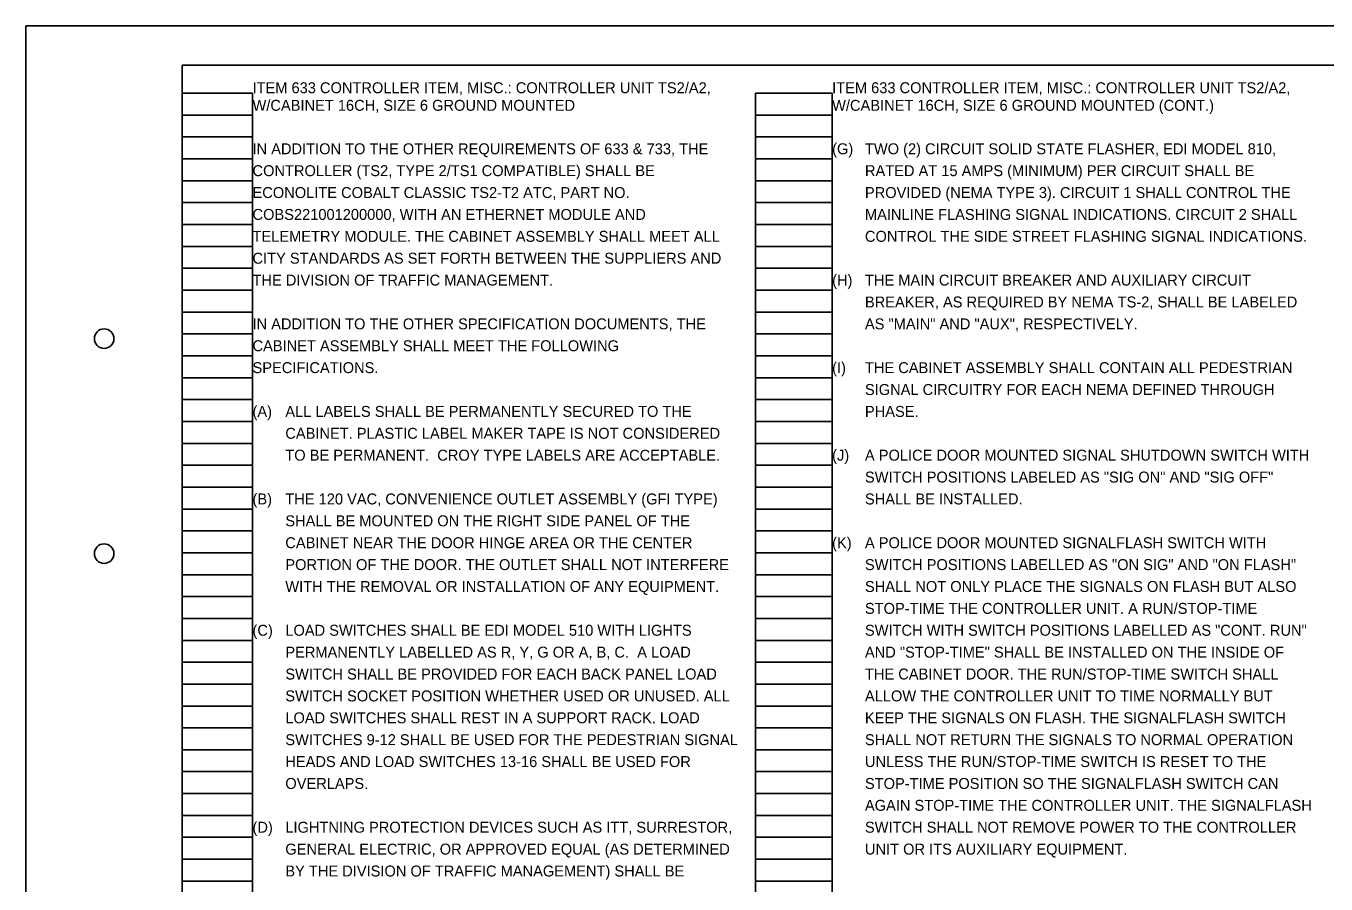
# Model space of a CAD drawing. Extents: x -38 to 65, y -51 to 25.
# Drawn here: x -0.51 to 16.14, y 3.51 to 14.49 of the extents above; entities that cross this region are included whole.
import ezdxf

# ---------------------------------------------------------------- set-up
doc = ezdxf.new("R2010")
doc.units = 0
for name, color, linetype in [('PF_P_Text', 7, 'Continuous'), ('SC_Scratch1', 7, 'Continuous'), ('SH_Cut_Line', 7, 'Continuous'), ('SH_Data', 7, 'Continuous')]:
    doc.layers.add(name, color=color, linetype=linetype)

msp = doc.modelspace()

# ---------------------------------------------------------------- linework, layer by layer
at = {"layer": 'PF_P_Text'}
msp.add_lwpolyline([(1.494, 13.992), (32.994, 13.992), (32.994, -7.008), (1.494, -7.008)], close=True, dxfattribs=at)
for centre in [(0.494, 10.492), (0.494, 7.742)]:
    msp.add_circle(centre, 0.125, dxfattribs=at)
at = {"layer": 'SC_Scratch1'}
for p, q in [((1.494, -6.528), (1.494, 13.632)), ((1.494, 13.632), (2.394, 13.632)), ((2.394, -6.528), (2.394, 13.632)), ((8.834, -6.528), (8.834, 13.632)), ((8.834, 13.632), (9.814, 13.632)), ((9.814, -6.528), (9.814, 13.632)), ((1.494, 13.352), (2.394, 13.352)), ((8.834, 13.352), (9.814, 13.352)), ((1.494, 13.072), (2.394, 13.072)), ((8.834, 13.072), (9.814, 13.072)), ((1.494, 12.792), (2.394, 12.792)), ((8.834, 12.792), (9.814, 12.792)), ((1.494, 12.512), (2.394, 12.512)), ((8.834, 12.512), (9.814, 12.512)), ((1.494, 12.232), (2.394, 12.232)), ((8.834, 12.232), (9.814, 12.232)), ((1.494, 11.952), (2.394, 11.952)), ((8.834, 11.952), (9.814, 11.952)), ((1.494, 11.672), (2.394, 11.672)), ((8.834, 11.672), (9.814, 11.672)), ((1.494, 11.392), (2.394, 11.392)), ((8.834, 11.392), (9.814, 11.392)), ((1.494, 11.112), (2.394, 11.112)), ((8.834, 11.112), (9.814, 11.112)), ((1.494, 10.832), (2.394, 10.832)), ((8.834, 10.832), (9.814, 10.832)), ((1.494, 10.552), (2.394, 10.552)), ((8.834, 10.552), (9.814, 10.552)), ((1.494, 10.272), (2.394, 10.272)), ((8.834, 10.272), (9.814, 10.272)), ((1.494, 9.992), (2.394, 9.992)), ((8.834, 9.992), (9.814, 9.992)), ((1.494, 9.712), (2.394, 9.712)), ((8.834, 9.712), (9.814, 9.712)), ((1.494, 9.432), (2.394, 9.432)), ((8.834, 9.432), (9.814, 9.432)), ((1.494, 9.152), (2.394, 9.152)), ((8.834, 9.152), (9.814, 9.152)), ((1.494, 8.872), (2.394, 8.872)), ((8.834, 8.872), (9.814, 8.872)), ((1.494, 8.592), (2.394, 8.592)), ((8.834, 8.592), (9.814, 8.592)), ((1.494, 8.312), (2.394, 8.312)), ((8.834, 8.312), (9.814, 8.312)), ((1.494, 8.032), (2.394, 8.032)), ((8.834, 8.032), (9.814, 8.032)), ((1.494, 7.752), (2.394, 7.752)), ((8.834, 7.752), (9.814, 7.752)), ((1.494, 7.472), (2.394, 7.472)), ((8.834, 7.472), (9.814, 7.472)), ((1.494, 7.192), (2.394, 7.192)), ((8.834, 7.192), (9.814, 7.192)), ((1.494, 6.912), (2.394, 6.912)), ((8.834, 6.912), (9.814, 6.912)), ((1.494, 6.632), (2.394, 6.632)), ((8.834, 6.632), (9.814, 6.632)), ((1.494, 6.352), (2.394, 6.352)), ((8.834, 6.352), (9.814, 6.352)), ((1.494, 6.072), (2.394, 6.072)), ((8.834, 6.072), (9.814, 6.072)), ((1.494, 5.792), (2.394, 5.792)), ((8.834, 5.792), (9.814, 5.792)), ((1.494, 5.512), (2.394, 5.512)), ((8.834, 5.512), (9.814, 5.512)), ((1.494, 5.232), (2.394, 5.232)), ((8.834, 5.232), (9.814, 5.232)), ((1.494, 4.952), (2.394, 4.952)), ((8.834, 4.952), (9.814, 4.952)), ((1.494, 4.672), (2.394, 4.672)), ((8.834, 4.672), (9.814, 4.672)), ((1.494, 4.392), (2.394, 4.392)), ((8.834, 4.392), (9.814, 4.392)), ((1.494, 4.112), (2.394, 4.112)), ((8.834, 4.112), (9.814, 4.112)), ((1.494, 3.832), (2.394, 3.832)), ((8.834, 3.832), (9.814, 3.832)), ((1.494, 3.552), (2.394, 3.552)), ((8.834, 3.552), (9.814, 3.552))]:
    msp.add_line(p, q, dxfattribs=at)
at = {"layer": 'SH_Cut_Line'}
msp.add_lwpolyline([(-0.506, -7.508), (33.494, -7.508), (33.494, 14.492), (-0.506, 14.492)], close=True, dxfattribs=at)

# ---------------------------------------------------------------- texts
at = {"layer": 'SH_Data'}
for s, p in [('ITEM 633 CONTROLLER ITEM, MISC.: CONTROLLER UNIT TS2/A2, ', (2.394, 13.632)), ('ITEM 633 CONTROLLER ITEM, MISC.: CONTROLLER UNIT TS2/A2, ', (9.814, 13.632)), ('W/CABINET 16CH, SIZE 6 GROUND MOUNTED', (2.394, 13.407)), ('W/CABINET 16CH, SIZE 6 GROUND MOUNTED (CONT.)', (9.814, 13.407)), ('IN ADDITION TO THE OTHER REQUIREMENTS OF 633 & 733, THE ', (2.394, 12.851)), ('(G)', (9.814, 12.851)), ('TWO (2) CIRCUIT SOLID STATE FLASHER, EDI MODEL 810, ', (10.234, 12.851)), ('CONTROLLER (TS2, TYPE 2/TS1 COMPATIBLE) SHALL BE ', (2.394, 12.571)), ('RATED AT 15 AMPS (MINIMUM) PER CIRCUIT SHALL BE ', (10.234, 12.571)), ('ECONOLITE COBALT CLASSIC TS2-T2 ATC, PART NO. ', (2.394, 12.291)), ('PROVIDED (NEMA TYPE 3). CIRCUIT 1 SHALL CONTROL THE ', (10.234, 12.291)), ('COBS221001200000, WITH AN ETHERNET MODULE AND ', (2.394, 12.011)), ('MAINLINE FLASHING SIGNAL INDICATIONS. CIRCUIT 2 SHALL ', (10.234, 12.011)), ('TELEMETRY MODULE. THE CABINET ASSEMBLY SHALL MEET ALL ', (2.394, 11.731)), ('CONTROL THE SIDE STREET FLASHING SIGNAL INDICATIONS.', (10.234, 11.731)), ('CITY STANDARDS AS SET FORTH BETWEEN THE SUPPLIERS AND ', (2.394, 11.451)), ('(H)', (9.814, 11.171)), ('THE DIVISION OF TRAFFIC MANAGEMENT.', (2.394, 11.171)), ('THE MAIN CIRCUIT BREAKER AND AUXILIARY CIRCUIT ', (10.234, 11.171)), ('BREAKER, AS REQUIRED BY NEMA TS-2, SHALL BE LABELED ', (10.234, 10.891)), ('IN ADDITION TO THE OTHER SPECIFICATION DOCUMENTS, THE ', (2.394, 10.611)), ('AS "MAIN" AND "AUX", RESPECTIVELY. ', (10.234, 10.611)), ('CABINET ASSEMBLY SHALL MEET THE FOLLOWING ', (2.394, 10.331)), ('SPECIFICATIONS.', (2.394, 10.051)), ('(I)', (9.814, 10.051)), ('THE CABINET ASSEMBLY SHALL CONTAIN ALL PEDESTRIAN ', (10.234, 10.051)), ('SIGNAL CIRCUITRY FOR EACH NEMA DEFINED THROUGH ', (10.234, 9.771)), ('(A)', (2.394, 9.491)), ('ALL LABELS SHALL BE PERMANENTLY SECURED TO THE ', (2.814, 9.491)), ('PHASE.', (10.234, 9.491)), ('CABINET. PLASTIC LABEL MAKER TAPE IS NOT CONSIDERED ', (2.814, 9.211)), ('TO BE PERMANENT.  CROY TYPE LABELS ARE ACCEPTABLE.', (2.814, 8.931)), ('(J)', (9.814, 8.931)), ('A POLICE DOOR MOUNTED SIGNAL SHUTDOWN SWITCH WITH ', (10.234, 8.931)), ('SWITCH POSITIONS LABELED AS "SIG ON" AND "SIG OFF" ', (10.234, 8.651)), ('(B)', (2.394, 8.371)), ('THE 120 VAC, CONVENIENCE OUTLET ASSEMBLY (GFI TYPE) ', (2.814, 8.371)), ('SHALL BE INSTALLED.', (10.234, 8.371)), ('SHALL BE MOUNTED ON THE RIGHT SIDE PANEL OF THE ', (2.814, 8.091)), ('CABINET NEAR THE DOOR HINGE AREA OR THE CENTER ', (2.814, 7.811)), ('(K)', (9.814, 7.811)), ('A POLICE DOOR MOUNTED SIGNALFLASH SWITCH WITH ', (10.234, 7.811)), ('PORTION OF THE DOOR. THE OUTLET SHALL NOT INTERFERE ', (2.814, 7.531)), ('SWITCH POSITIONS LABELLED AS "ON SIG" AND "ON FLASH" ', (10.234, 7.531)), ('WITH THE REMOVAL OR INSTALLATION OF ANY EQUIPMENT.', (2.814, 7.251)), ('SHALL NOT ONLY PLACE THE SIGNALS ON FLASH BUT ALSO ', (10.234, 7.251)), ('STOP-TIME THE CONTROLLER UNIT. A RUN/STOP-TIME ', (10.234, 6.971)), ('(C)', (2.394, 6.691)), ('LOAD SWITCHES SHALL BE EDI MODEL 510 WITH LIGHTS ', (2.814, 6.691)), ('SWITCH WITH SWITCH POSITIONS LABELLED AS "CONT. RUN" ', (10.234, 6.691)), ('PERMANENTLY LABELLED AS R, Y, G OR A, B, C.  A LOAD ', (2.814, 6.411)), ('AND "STOP-TIME" SHALL BE INSTALLED ON THE INSIDE OF ', (10.234, 6.411)), ('SWITCH SHALL BE PROVIDED FOR EACH BACK PANEL LOAD ', (2.814, 6.131)), ('THE CABINET DOOR. THE RUN/STOP-TIME SWITCH SHALL ', (10.234, 6.131)), ('SWITCH SOCKET POSITION WHETHER USED OR UNUSED. ALL ', (2.814, 5.851)), ('ALLOW THE CONTROLLER UNIT TO TIME NORMALLY BUT ', (10.234, 5.851)), ('LOAD SWITCHES SHALL REST IN A SUPPORT RACK. LOAD ', (2.814, 5.571)), ('KEEP THE SIGNALS ON FLASH. THE SIGNALFLASH SWITCH ', (10.234, 5.571)), ('SWITCHES 9-12 SHALL BE USED FOR THE PEDESTRIAN SIGNAL ', (2.814, 5.291)), ('SHALL NOT RETURN THE SIGNALS TO NORMAL OPERATION ', (10.234, 5.291)), ('HEADS AND LOAD SWITCHES 13-16 SHALL BE USED FOR ', (2.814, 5.011)), ('UNLESS THE RUN/STOP-TIME SWITCH IS RESET TO THE ', (10.234, 5.011)), ('OVERLAPS.', (2.814, 4.731)), ('STOP-TIME POSITION SO THE SIGNALFLASH SWITCH CAN ', (10.234, 4.731)), ('AGAIN STOP-TIME THE CONTROLLER UNIT. THE SIGNALFLASH ', (10.234, 4.451)), ('(D)', (2.394, 4.171)), ('LIGHTNING PROTECTION DEVICES SUCH AS ITT, SURRESTOR, ', (2.814, 4.171)), ('SWITCH SHALL NOT REMOVE POWER TO THE CONTROLLER ', (10.234, 4.171)), ('GENERAL ELECTRIC, OR APPROVED EQUAL (AS DETERMINED ', (2.814, 3.891)), ('UNIT OR ITS AUXILIARY EQUIPMENT.', (10.234, 3.891)), ('BY THE DIVISION OF TRAFFIC MANAGEMENT) SHALL BE ', (2.814, 3.611))]:
    msp.add_text(s, height=0.14, dxfattribs=at).set_placement(p)

doc.saveas('drawing.dxf')
